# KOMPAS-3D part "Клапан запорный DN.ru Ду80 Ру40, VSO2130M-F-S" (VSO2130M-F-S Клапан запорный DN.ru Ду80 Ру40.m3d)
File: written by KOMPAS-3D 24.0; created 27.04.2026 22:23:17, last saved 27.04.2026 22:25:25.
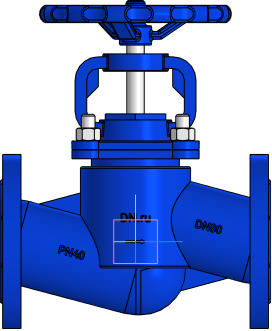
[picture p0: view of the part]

Document properties: Автор: DN.ru; Полное имя файла: C:\Работа\ГОТОВЫЕ ИСХОДНИКИ\VSO2130M-F-S Клапан запорный сальниковый DN.ru Ду15-100 Ру40\DN80\VSO2130M-F-S Клапан запорный DN.ru Ду80 Ру40.m3d

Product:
- Part/product: Клапан запорный DN.ru Ду80 Ру40  | designation VSO2130M-F-S
    Масса: 30
    Раздел спецификации: Прочие изделия
    Примечание: D090-01986

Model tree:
1. Операция без истории:1

Referenced files in C:\Program Files\ASCON\KOMPAS-3D v24\Libs\Pipeline\: StylesTemplate.a3d, TemplateHPH, InsulationStylesTemplate.a3d, Insulation
Referenced files in C:\Program Files\ASCON\KOMPAS-3D v24\Templates\: Констр. чертеж А3 гориз. перв. лист.cdt
Referenced files in C:\Работа\ГОТОВЫЕ ИСХОДНИКИ\VSO2130M-F-S Клапан запорный сальниковый DN.ru Ду15-100 Ру40\исходные материалы\DN80\: 
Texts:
  Отводы ГОСТ 17375-2001
  Констр. чертеж А3 гориз. перв. лист.cdt
  VSO2130M-F-S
